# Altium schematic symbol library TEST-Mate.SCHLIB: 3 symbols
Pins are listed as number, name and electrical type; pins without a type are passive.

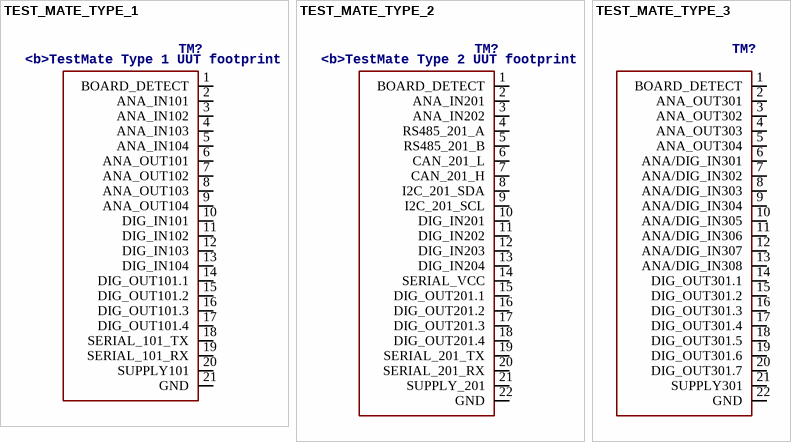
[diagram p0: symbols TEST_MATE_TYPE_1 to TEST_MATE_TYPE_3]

## TEST_MATE_TYPE_1
designator TM?, comment <b>TestMate Type 1 UUT footprint
footprint TEST_MATE_TYPE_1
pins: 1 BOARD_DETECT, 2 ANA_IN101, 3 ANA_IN102, 4 ANA_IN103, 5 ANA_IN104, 6 ANA_OUT101, 7 ANA_OUT102, 8 ANA_OUT103, 9 ANA_OUT104, 10 DIG_IN101, 11 DIG_IN102, 12 DIG_IN103, 13 DIG_IN104, 14 DIG_OUT101.1, 15 DIG_OUT101.2, 16 DIG_OUT101.3, 17 DIG_OUT101.4, 18 SERIAL_101_TX, 19 SERIAL_101_RX, 20 SUPPLY101, 21 GND

## TEST_MATE_TYPE_2
designator TM?, comment <b>TestMate Type 2 UUT footprint
footprint TEST_MATE_TYPE_2
pins: 1 BOARD_DETECT, 2 ANA_IN201, 3 ANA_IN202, 4 RS485_201_A, 5 RS485_201_B, 6 CAN_201_L, 7 CAN_201_H, 8 I2C_201_SDA, 9 I2C_201_SCL, 10 DIG_IN201, 11 DIG_IN202, 12 DIG_IN203, 13 DIG_IN204, 14 SERIAL_VCC, 15 DIG_OUT201.1, 16 DIG_OUT201.2, 17 DIG_OUT201.3, 18 DIG_OUT201.4, 19 SERIAL_201_TX, 20 SERIAL_201_RX, 21 SUPPLY_201, 22 GND

## TEST_MATE_TYPE_3
designator TM?
footprint TEST_MATE_TYPE_3
pins: 1 BOARD_DETECT, 2 ANA_OUT301, 3 ANA_OUT302, 4 ANA_OUT303, 5 ANA_OUT304, 6 ANA/DIG_IN301, 7 ANA/DIG_IN302, 8 ANA/DIG_IN303, 9 ANA/DIG_IN304, 10 ANA/DIG_IN305, 11 ANA/DIG_IN306, 12 ANA/DIG_IN307, 13 ANA/DIG_IN308, 14 DIG_OUT301.1, 15 DIG_OUT301.2, 16 DIG_OUT301.3, 17 DIG_OUT301.4, 18 DIG_OUT301.5, 19 DIG_OUT301.6, 20 DIG_OUT301.7, 21 SUPPLY301, 22 GND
